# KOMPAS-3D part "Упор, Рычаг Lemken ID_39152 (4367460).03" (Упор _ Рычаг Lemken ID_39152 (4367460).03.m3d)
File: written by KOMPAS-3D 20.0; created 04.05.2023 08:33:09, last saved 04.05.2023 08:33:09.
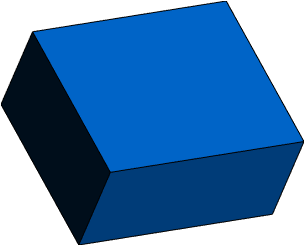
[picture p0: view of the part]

Document properties: Автор: factory; Полное имя файла: C:\Users\factory\Desktop\Чертежи\Рычаг Lemken ID_39152 (4367460)\Упор _ Рычаг Lemken ID_39152 (4367460).03.m3d

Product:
- Part/product: Упор  | designation Рычаг Lemken ID_39152 (4367460).03
    Материал: Лист$d10х700х5000 ГОСТ 19903-2015;295-09Г2 ГОСТ 19281-2014$ (density 7850 kg/m3)
    Масса: 0.02669
    source file: Упор _ Рычаг Lemken ID_39152 (4367460).03_Чертёж.cdw

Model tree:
1. Эскиз:1
2. Элемент выдавливания:1  (labels: Лист$d10х700х5000 ГОСТ 19903-2015;295-09Г2 ГОСТ 19281-2014$)
     Расстояние 1 = 10

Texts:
  Рычаг Lemken ID_39152 (4367460).03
